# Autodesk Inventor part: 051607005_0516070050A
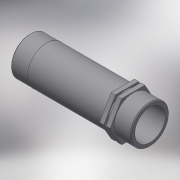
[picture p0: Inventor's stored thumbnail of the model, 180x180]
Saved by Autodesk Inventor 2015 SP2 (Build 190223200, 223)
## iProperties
Created: 2017-05
Part Number: 051607005_0516070050A
Material: Generic
Description: PLASSON RISER 1/2"-1/2"
Document SubType Name: Modeling
Designer: KIM
Mass: 20.3153 g
Surface Area: 184.457 cm^2
Volume: 20.3153 cm^3
Density: 1 g/cm^3
Appearance: Default
Author: KIM
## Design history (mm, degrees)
derived "051607.ipt"
feature "Solid1::051607.ipt"
tag "TaggingFeature1"
body "Solid1"
other parameters: "d1" = 20.955, "d2" = 22, "d3" = 16.764, "d5" = 17, "d6" = 4.25, "d8" = 0.85, "d12" = 0, "d13" = 2.125, "d15" = 17, "d17" = 0, "d18" = 20.955, "R_" = 20.955, "E_" = 22, "l_2" = 17, "R_1" = 20.955
